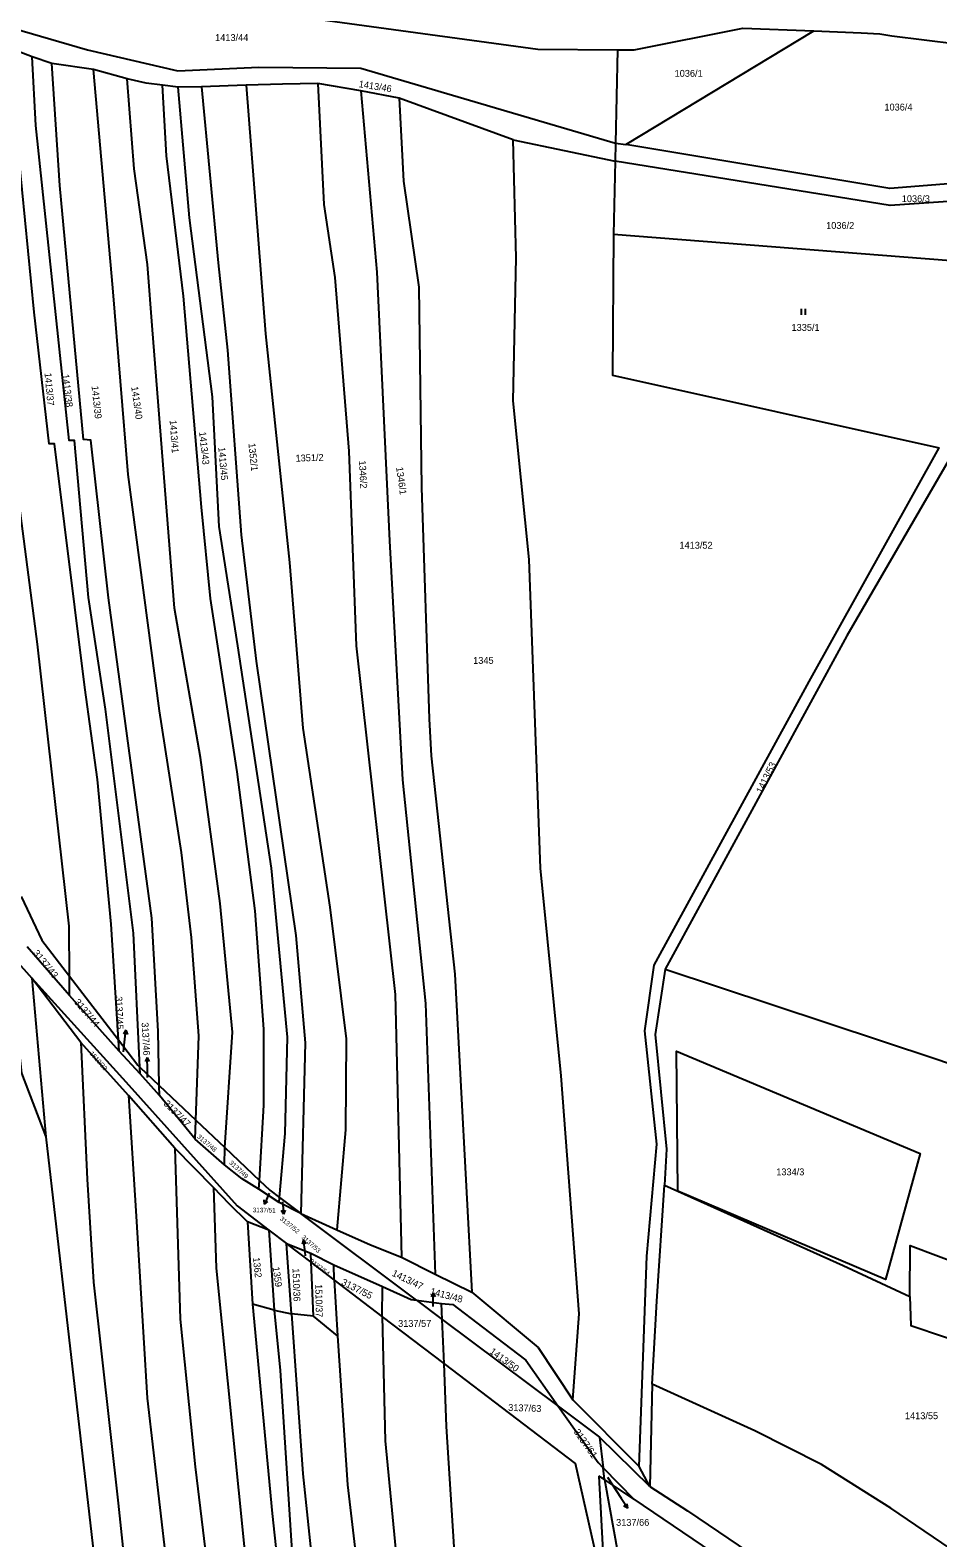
# Model space of a CAD drawing. Extents: x -776734 to -748832, y -1118122 to -976986.
# Drawn here: x -752178.5 to -751953.8, y -1116225.4 to -1115852 of the extents above; entities that cross this region are included whole.
import ezdxf

# ---------------------------------------------------------------- set-up
doc = ezdxf.new("R2010")
doc.units = 0
for name, color, linetype in [('KM_Hranice parcel', 7, 'Continuous'), ('KM_Parcelní čísla', 7, 'Continuous'), ('KM_Pop  PČ popisy', 7, 'Continuous'), ('KM_Značky kultur', 7, 'Continuous')]:
    doc.layers.add(name, color=color, linetype=linetype)

msp = doc.modelspace()

# ---------------------------------------------------------------- linework, layer by layer
at = {"layer": 'KM_Hranice parcel'}
for p, q in [((-752030.97, -1115880.3), (-751984.47, -1115852.18)), ((-752177.95, -1115858.57), (-752182.25, -1115856.92)), ((-752033.09, -1115856.85), (-752033.58, -1115879.94)), ((-752173.09, -1115860.22), (-752177.95, -1115858.57)), ((-752162.78, -1115861.71), (-752173.09, -1115860.22)), ((-752154.46, -1115864.03), (-752162.78, -1115861.71)), ((-752141.8, -1115866.12), (-752145.67, -1115865.62)), ((-752125, -1115865.59), (-752136.05, -1115866)), ((-752096.62, -1115867.02), (-752107.22, -1115865.22)), ((-752136.05, -1115866), (-752141.8, -1115866.12)), ((-752087.09, -1115868.83), (-752096.62, -1115867.02)), ((-752058.89, -1115879.11), (-752087.09, -1115868.83)), ((-752058.89, -1115879.11), (-752033.67, -1115884.41)), ((-752033.58, -1115879.94), (-752033.67, -1115884.41)), ((-752033.58, -1115879.94), (-752030.97, -1115880.3)), ((-752033.67, -1115884.41), (-752034.06, -1115902.59)), ((-751928.79, -1115910.84), (-752034.06, -1115902.59)), ((-752168.72, -1116091.06), (-752179.16, -1116078.98)), ((-752165.95, -1116102.71), (-752178.05, -1116086.74)), ((-752178.05, -1116086.74), (-752174.6, -1116126.07)), ((-752168.72, -1116091.06), (-752168.74, -1116086.25)), ((-752168.74, -1116086.25), (-752156.62, -1116102.03)), ((-752156.44, -1116104.86), (-752168.72, -1116091.06)), ((-752154.15, -1116115.8), (-752165.95, -1116102.71)), ((-752156.44, -1116104.86), (-752156.62, -1116102.03)), ((-752151.2, -1116110.49), (-752156.44, -1116104.86)), ((-752151.2, -1116110.49), (-752151.28, -1116108.79)), ((-752151.28, -1116108.79), (-752146.49, -1116113.33)), ((-752146.44, -1116115.83), (-752151.2, -1116110.49)), ((-752142.68, -1116128.9), (-752154.15, -1116115.8)), ((-752146.44, -1116115.83), (-752146.49, -1116113.33)), ((-752146.49, -1116113.33), (-752137.43, -1116121.93)), ((-752137.58, -1116126.64), (-752146.44, -1116115.83)), ((-752137.58, -1116126.64), (-752137.43, -1116121.93)), ((-752137.43, -1116121.93), (-752130.28, -1116128.71)), ((-752130.38, -1116133), (-752137.58, -1116126.64)), ((-752133.11, -1116138.65), (-752142.68, -1116128.9)), ((-752130.38, -1116133), (-752130.28, -1116128.71)), ((-752130.28, -1116128.71), (-752121.7, -1116136.85)), ((-752121.83, -1116139), (-752121.7, -1116136.85)), ((-752116.86, -1116142.29), (-752121.83, -1116139)), ((-752116.86, -1116142.29), (-752116.7, -1116141.11)), ((-752116.7, -1116141.11), (-752111.48, -1116145.02)), ((-752111.48, -1116145.02), (-752116.86, -1116142.29)), ((-752111.48, -1116145.02), (-752102.54, -1116149.13)), ((-752082.85, -1116166.49), (-752111.48, -1116145.02)), ((-752119.4, -1116149.15), (-752124.69, -1116147.15)), ((-752124.69, -1116147.15), (-752123.43, -1116167.51)), ((-752119.4, -1116149.15), (-752118.05, -1116168.97)), ((-752119.4, -1116149.15), (-752115.01, -1116152.49)), ((-752108.91, -1116157.14), (-752115.01, -1116152.49)), ((-752113.79, -1116169.94), (-752115.01, -1116152.49)), ((-752115.01, -1116152.49), (-752109.01, -1116154.88)), ((-752108.91, -1116157.14), (-752109.01, -1116154.88)), ((-752109.01, -1116154.88), (-752103.32, -1116157.78)), ((-752086.57, -1116155.88), (-752078.17, -1116160.09)), ((-752103.22, -1116161.47), (-752108.91, -1116157.14)), ((-752108.32, -1116170.48), (-752108.91, -1116157.14)), ((-752103.22, -1116161.47), (-752103.32, -1116157.78)), ((-752103.32, -1116157.78), (-752091.21, -1116163.17)), ((-752078.17, -1116160.09), (-752069.09, -1116164.51)), ((-752103.22, -1116161.47), (-752102.39, -1116175.31)), ((-752091.33, -1116170.52), (-752103.22, -1116161.47)), ((-752091.33, -1116170.52), (-752091.21, -1116163.17)), ((-752118.05, -1116168.97), (-752123.43, -1116167.51)), ((-752082.85, -1116166.49), (-752076.45, -1116171.28)), ((-752082.85, -1116166.49), (-752076.61, -1116167.35)), ((-752076.45, -1116171.28), (-752076.61, -1116167.35)), ((-752118.05, -1116168.97), (-752113.79, -1116169.94)), ((-752108.32, -1116170.48), (-752113.79, -1116169.94)), ((-752102.39, -1116175.31), (-752108.32, -1116170.48)), ((-752076.01, -1116182.2), (-752091.33, -1116170.52)), ((-752076.45, -1116171.28), (-752047.75, -1116192.79)), ((-752076.01, -1116182.2), (-752076.45, -1116171.28)), ((-752024.53, -1116187.32), (-752025.07, -1116212.63)), ((-752047.75, -1116192.79), (-752037.56, -1116200.43)), ((-752027.7, -1116207.75), (-752044.12, -1116191.2)), ((-752025.07, -1116212.63), (-752037.56, -1116200.43)), ((-752037.56, -1116200.43), (-752036.63, -1116208.05)), ((-752036.63, -1116208.05), (-752029.02, -1116215.81)), ((-752036.28, -1116210.9), (-752036.63, -1116208.05)), ((-752025.07, -1116212.63), (-752027.7, -1116207.75)), ((-752036.28, -1116210.9), (-752037.72, -1116210.11)), ((-752029.02, -1116215.81), (-752036.28, -1116210.9)), ((-752029.02, -1116215.81), (-751967.61, -1116257.33))]:
    msp.add_line(p, q, dxfattribs=at)
for points in [[(-752244.75, -1115830.41), (-752239.78, -1115832.43), (-752214.29, -1115840.49), (-752189.58, -1115849.47), (-752164.25, -1115856.85), (-752141.87, -1115862.01), (-752121.83, -1115861.15), (-752096.62, -1115861.4), (-752033.58, -1115879.94)], [(-752244.75, -1115830.41), (-752052.79, -1115856.72), (-752033.09, -1115856.85)], [(-752168.74, -1116086.25), (-752168.78, -1116073.92), (-752176.6, -1116004.07), (-752182.5, -1115958.91), (-752185.13, -1115959.87), (-752188.35, -1115934.16), (-752191.68, -1115873.68), (-752193.05, -1115853.24)], [(-752033.09, -1115856.85), (-752028.93, -1115856.83), (-752002.08, -1115851.48), (-751984.47, -1115852.18)], [(-751984.47, -1115852.18), (-751972.72, -1115852.64), (-751968.12, -1115852.9), (-751965.14, -1115853.34), (-751941.2, -1115856.37), (-751924.31, -1115858.52)], [(-752156.62, -1116102.03), (-752158.4, -1116073.41), (-752161.79, -1116037.58), (-752164.91, -1116014.77), (-752172.39, -1115954.41), (-752173.72, -1115954.45), (-752177.46, -1115921.84), (-752181.92, -1115876.22), (-752182.25, -1115856.92)], [(-752151.28, -1116108.79), (-752152.88, -1116075.63), (-752159.78, -1116020.18), (-752163.99, -1115992.47), (-752167.49, -1115953.58), (-752168.78, -1115953.58), (-752177.03, -1115875.55), (-752177.95, -1115858.57)], [(-752146.49, -1116113.33), (-752146.78, -1116099.86), (-752148.31, -1116071.93), (-752159.05, -1115992.53), (-752163.45, -1115953.53), (-752165.28, -1115953.39), (-752171.13, -1115890.47), (-752173.09, -1115860.22)], [(-752137.43, -1116121.93), (-752136.74, -1116101.01), (-752138.53, -1116076.68), (-752140.96, -1116055.66), (-752146.41, -1116020.58), (-752154.2, -1115961.99), (-752157.99, -1115915.81), (-752162.78, -1115861.71)], [(-752145.67, -1115865.62), (-752149.75, -1115865.08), (-752154.46, -1115864.03)], [(-752130.28, -1116128.71), (-752128.37, -1116100.14), (-752131.39, -1116068.3), (-752136.28, -1116032.13), (-752142.74, -1115995.11), (-752148.2, -1115926.23), (-752149.42, -1115909.99), (-752152.72, -1115886.34), (-752154.46, -1115864.03)], [(-752121.7, -1116136.85), (-752120.61, -1116118.19), (-752120.6, -1116099.39), (-752122.77, -1116070.07), (-752127.23, -1116035.69), (-752133.78, -1115992.73), (-752136.02, -1115970.08), (-752140.48, -1115917.89), (-752144.73, -1115883.11), (-752145.67, -1115865.62)], [(-752107.22, -1115865.22), (-752116.02, -1115865.32), (-752125, -1115865.59)], [(-752125, -1115865.59), (-752120.18, -1115927.16), (-752114.22, -1115983.82), (-752110.98, -1116024.87), (-752104.27, -1116069.18), (-752100.27, -1116101.79), (-752100.37, -1116124.32), (-752102.54, -1116149.13)], [(-752107.22, -1115865.22), (-752105.74, -1115895.16), (-752103.03, -1115913.21), (-752099.59, -1115956.21), (-752097.76, -1116004.48), (-752088.12, -1116090.85), (-752086.57, -1116155.88)], [(-752116.7, -1116141.11), (-752115.32, -1116125.21), (-752114.73, -1116101.39), (-752118.68, -1116059.51), (-752127.02, -1116004.45), (-752131.71, -1115974.88), (-752133.32, -1115942.8), (-752139.03, -1115898.44), (-752141.8, -1115866.12)], [(-752136.05, -1115866), (-752131.91, -1115909.64), (-752129.64, -1115931.25), (-752126.23, -1115976.95), (-752122.5, -1116008.29), (-752112.69, -1116076.23), (-752110.42, -1116102.8), (-752111.48, -1116145.02)], [(-752096.62, -1115867.02), (-752092.66, -1115911.92), (-752089.53, -1115978.49), (-752086.28, -1116037.63), (-752080.6, -1116093.06), (-752078.17, -1116160.09)], [(-752087.09, -1115868.83), (-752086.04, -1115889.38), (-752082.28, -1115915.65), (-752081.57, -1115965.22), (-752079.66, -1116022.57), (-752079.18, -1116031.72), (-752073.37, -1116085.74), (-752069.09, -1116164.51)], [(-752044.12, -1116191.2), (-752042.6, -1116169.93), (-752046.98, -1116110.96), (-752052.13, -1116059.51), (-752054.9, -1115983.09), (-752058.9, -1115943.74), (-752058.14, -1115908.39), (-752058.89, -1115879.11)], [(-751921.23, -1115887.66), (-751965.69, -1115891.2), (-752030.97, -1115880.3)], [(-751921.39, -1115892.38), (-751965.58, -1115895.4), (-752033.67, -1115884.41)], [(-752034.06, -1115902.59), (-752034.28, -1115937.4), (-751953.42, -1115955.46)], [(-752027.7, -1116207.75), (-752025.8, -1116155.61), (-752023.34, -1116127.92), (-752026.32, -1116099.82), (-752023.96, -1116083.51), (-751985.61, -1116013.3), (-751953.42, -1115955.46)], [(-751949.72, -1115956.2), (-751976.28, -1116001.97), (-752021.26, -1116084.5)], [(-752180.64, -1116066.51), (-752175.58, -1116077.34), (-752168.74, -1116086.25)], [(-752184.07, -1116078.11), (-752180.63, -1116110.3), (-752174.6, -1116126.07)], [(-752184.07, -1116078.11), (-752182.11, -1116082.25), (-752178.05, -1116086.74)], [(-752021.26, -1116084.5), (-752023.78, -1116100.69), (-752020.93, -1116129.09), (-752021.44, -1116138.03)], [(-752021.26, -1116084.5), (-751954.28, -1116106.76), (-751878.91, -1116132.52), (-751849.54, -1116138.46), (-751864.28, -1116164.24)], [(-752178.05, -1116086.74), (-752154.81, -1116112.45), (-752127.25, -1116143.17), (-752119.4, -1116149.15)], [(-752165.95, -1116102.71), (-752164.33, -1116136.55), (-752162.74, -1116162.09), (-752156.71, -1116216.83), (-752151.57, -1116265.42), (-752144.17, -1116332.21), (-752140.15, -1116365.11), (-752135.5, -1116393.73), (-752128.72, -1116429.01), (-752127.84, -1116468.06), (-752124.6, -1116508.67), (-752124.98, -1116521.91), (-752135.82, -1116514.55)], [(-752156.62, -1116102.03), (-752151.81, -1116108.29), (-752151.28, -1116108.79)], [(-752018.13, -1116139.48), (-752018.5, -1116104.86), (-751958.18, -1116130.17), (-751966.75, -1116161.42), (-752018.13, -1116139.48)], [(-752154.15, -1116115.8), (-752152.25, -1116145.68), (-752149.48, -1116190.78), (-752136.91, -1116299.1), (-752126.9, -1116382.45), (-752120.61, -1116430.42), (-752115.56, -1116478.78), (-752113, -1116508.67), (-752115.4, -1116518.05), (-752116.87, -1116525.29), (-752111.35, -1116567.65), (-752106.73, -1116619.27), (-752103.92, -1116654.37), (-752098.48, -1116721.23)], [(-752174.6, -1116126.07), (-752166.87, -1116192.95), (-752158.85, -1116263.38), (-752156.71, -1116303.51), (-752151.3, -1116341.33), (-752138.37, -1116429.18), (-752136.5, -1116462.73), (-752135.89, -1116484.99), (-752135.82, -1116514.55)], [(-752142.68, -1116128.9), (-752141.35, -1116171.25), (-752137.64, -1116207.78), (-752125.81, -1116305.36), (-752116.18, -1116388.17), (-752111.3, -1116422.2), (-752105.09, -1116478.91), (-752101.86, -1116522.09), (-752098.52, -1116553.17), (-752095.76, -1116613.19), (-752089.84, -1116678.02), (-752084.67, -1116717.26)], [(-752121.83, -1116139), (-752125.96, -1116136.49), (-752130.38, -1116133)], [(-752121.7, -1116136.85), (-752119.14, -1116139.28), (-752116.7, -1116141.11)], [(-752024.53, -1116187.32), (-752023.32, -1116166.75), (-752021.44, -1116138.03)], [(-752021.44, -1116138.03), (-752018.13, -1116139.48), (-751977.19, -1116157.92), (-751960.75, -1116165.61)], [(-752124.69, -1116147.15), (-752129.09, -1116142.72), (-752133.11, -1116138.65)], [(-752133.11, -1116138.65), (-752132.42, -1116158.63), (-752125.46, -1116227.53), (-752117.44, -1116292.6), (-752110.09, -1116359.1), (-752100.17, -1116437.88), (-752095.69, -1116474.85), (-752092.89, -1116524.7), (-752091.68, -1116540.31), (-752089.41, -1116561.36), (-752086.83, -1116606.81), (-752085.92, -1116622.13), (-752080.62, -1116669.02), (-752074.51, -1116714.34)], [(-752102.54, -1116149.13), (-752094.23, -1116152.79), (-752086.57, -1116155.88)], [(-751960.75, -1116165.61), (-751960.66, -1116152.95), (-751911.53, -1116171.43), (-751886.14, -1116180.76)], [(-752091.21, -1116163.17), (-752084.11, -1116166.31), (-752082.85, -1116166.49)], [(-752123.43, -1116167.51), (-752118.52, -1116219.33), (-752113.21, -1116269.11), (-752107.73, -1116310.35), (-752101.77, -1116359.1), (-752096.05, -1116404.78), (-752094.04, -1116419.92), (-752089.53, -1116463.02), (-752087.28, -1116481.06), (-752084.46, -1116522.63), (-752080.99, -1116553.57), (-752078.09, -1116601.02), (-752076.96, -1116622.69), (-752073.5, -1116656.29), (-752069.23, -1116691), (-752065.65, -1116711.79)], [(-752076.61, -1116167.35), (-752073.8, -1116167.62), (-752066.53, -1116173.22), (-752055.78, -1116181.41), (-752047.75, -1116192.79)], [(-752069.09, -1116164.51), (-752052.7, -1116178.22), (-752044.12, -1116191.2)], [(-751960.75, -1116165.61), (-751960.5, -1116172.81), (-751943.76, -1116178.41), (-751909.07, -1116192.07), (-751889.54, -1116201.98)], [(-752118.05, -1116168.97), (-752116.6, -1116183.9), (-752113.43, -1116232.37), (-752111.41, -1116249.39), (-752105.93, -1116293.43), (-752094.61, -1116381.9), (-752089.13, -1116422.48), (-752085.67, -1116453.92), (-752083.17, -1116484.31), (-752079.8, -1116525.75), (-752076.73, -1116555.18), (-752075.76, -1116570.66), (-752072.49, -1116627.11), (-752067.87, -1116674.42), (-752062.04, -1116710.75)], [(-752113.79, -1116169.94), (-752110.94, -1116209.53), (-752105.69, -1116259.78), (-752098.36, -1116323.38), (-752088.4, -1116395.97), (-752084.26, -1116424.45), (-752079.29, -1116481.41), (-752075.15, -1116529.39), (-752073.28, -1116546.6), (-752071, -1116582.62), (-752068.09, -1116623.34), (-752064.5, -1116659.9), (-752061.67, -1116685.28), (-752057.71, -1116708.78)], [(-752091.33, -1116170.52), (-752091.03, -1116184.27), (-752090.6, -1116201.38), (-752086.96, -1116239.19), (-752080.77, -1116290.76), (-752075.21, -1116336.04), (-752068.84, -1116386.33), (-752066.21, -1116414.12), (-752057.2, -1116499.5), (-752055.65, -1116524.83), (-752053.1, -1116572.93), (-752049.91, -1116617.58), (-752045.45, -1116660.22), (-752038.63, -1116700.1)], [(-752102.39, -1116175.31), (-752099.9, -1116212.26), (-752092.02, -1116279.66), (-752084.55, -1116341.12), (-752078.68, -1116390.57), (-752072.19, -1116452.52), (-752067.79, -1116496.71), (-752063.39, -1116563.68), (-752056.16, -1116640.19), (-752048.54, -1116704.61)], [(-752017.9, -1116408.76), (-752023.63, -1116341.02), (-752028.14, -1116300.58), (-752036.89, -1116236.27), (-752043.49, -1116206.97), (-752076.01, -1116182.2)], [(-752024.24, -1116693.56), (-752035.71, -1116608.37), (-752037.73, -1116585.85), (-752038.36, -1116560.02), (-752042.15, -1116500.69), (-752046.45, -1116458.81), (-752052.14, -1116403.78), (-752059.97, -1116326.66), (-752069.01, -1116269.52), (-752073.5, -1116227.61), (-752075.37, -1116197.8), (-752076.01, -1116182.2)], [(-751906.88, -1116257.83), (-751965.43, -1116218.03), (-751982.56, -1116207.19), (-751999.04, -1116198.88), (-752024.53, -1116187.32)], [(-752047.75, -1116192.79), (-752037.9, -1116206.75), (-752036.63, -1116208.05)], [(-752037.72, -1116210.11), (-752036.58, -1116231.72), (-752026.84, -1116301.37), (-752020.12, -1116357.18), (-752017.9, -1116408.76)], [(-752036.28, -1116210.9), (-752031.83, -1116235.64), (-752023.06, -1116294.18)], [(-752025.07, -1116212.63), (-752015.78, -1116218.71), (-751975.31, -1116246.13), (-751917.35, -1116277.21), (-751898.52, -1116290.39)]]:
    msp.add_lwpolyline(points, dxfattribs=at)
at = {"layer": 'KM_Pop  PČ popisy'}
for p, q in [((-752154.776, -1116099.655), (-752155.379, -1116100.599)), ((-752155.09, -1116102.64), (-752154.776, -1116099.655)), ((-752154.776, -1116099.655), (-752154.383, -1116100.704)), ((-752155.34, -1116105), (-752155.09, -1116102.64)), ((-752149.525, -1116106.401), (-752149.99, -1116107.419)), ((-752149.42, -1116109.4), (-752149.525, -1116106.401)), ((-752149.525, -1116106.401), (-752148.989, -1116107.384)), ((-752149.37, -1116111.38), (-752149.42, -1116109.4)), ((-752120.443, -1116142.772), (-752120.512, -1116141.655)), ((-752119.27, -1116140.01), (-752120.443, -1116142.772)), ((-752120.443, -1116142.772), (-752119.59, -1116142.046)), ((-752119.26, -1116139.99), (-752119.27, -1116140.01)), ((-752115.666, -1116145.245), (-752116.269, -1116144.301)), ((-752115.99, -1116142.17), (-752115.98, -1116142.26)), ((-752115.98, -1116142.26), (-752115.666, -1116145.245)), ((-752115.666, -1116145.245), (-752115.273, -1116144.196)), ((-752110.766, -1116151.571), (-752111.141, -1116152.626)), ((-752110.4, -1116154.55), (-752110.766, -1116151.571)), ((-752110.766, -1116151.571), (-752110.147, -1116152.504)), ((-752110.28, -1116155.56), (-752110.4, -1116154.55)), ((-752078.68, -1116164.669), (-752079.181, -1116165.67)), ((-752078.68, -1116167.67), (-752078.68, -1116164.669)), ((-752078.68, -1116164.669), (-752078.179, -1116165.67)), ((-752078.68, -1116168.08), (-752078.68, -1116167.67)), ((-752035.55, -1116210.36), (-752032.16, -1116215.53)), ((-752032.16, -1116215.53), (-752030.526, -1116218.047)), ((-752030.526, -1116218.047), (-752031.491, -1116217.48)), ((-752030.526, -1116218.047), (-752030.651, -1116216.934))]:
    msp.add_line(p, q, dxfattribs=at)
at = {"layer": 'KM_Značky kultur'}
for p, q in [((-751987.511, -1115922.51), (-751987.511, -1115921.01)), ((-751986.51, -1115922.51), (-751986.51, -1115921.01))]:
    msp.add_line(p, q, dxfattribs=at)

# ---------------------------------------------------------------- texts
at = {"layer": 'KM_Parcelní čísla'}
for s, p in [('1413/44', (-752132.67, -1115854.66)), ('1036/1', (-752018.94, -1115863.52)), ('1036/4', (-751967.01, -1115871.88)), ('1036/3', (-751962.71, -1115894.57)), ('1036/2', (-751981.43, -1115901.2)), ('1335/1', (-751990, -1115926.45)), ('1413/52', (-752017.74, -1115980.4)), ('1345', (-752068.8, -1116008.92)), ('1334/3', (-751993.78, -1116135.59)), ('3137/57', (-752087.38, -1116173.13)), ('1413/55', (-751961.93, -1116195.99)), ('3137/66', (-752033.42, -1116222.398))]:
    msp.add_text(s, height=1.7, dxfattribs=at).set_placement(p)
for s, height, rotation, p in [('1413/46', 1.7, 351, (-752097.212, -1115866.079)), ('1413/37', 1.7, 275, (-752174.896, -1115936.884)), ('1413/38', 1.7, 277, (-752170.543, -1115937.283)), ('1413/39', 1.7, 275.999997, (-752163.255, -1115940.128)), ('1413/40', 1.7, 278, (-752153.441, -1115940.328)), ('1413/41', 1.7, 274, (-752143.927, -1115948.599)), ('1413/43', 1.7, 275.999997, (-752136.635, -1115951.488)), ('1352/1', 1.7, 275.999997, (-752124.435, -1115954.348)), ('1413/45', 1.7, 275, (-752131.886, -1115955.324)), ('1351/2', 1.7, 2, (-752112.74, -1115958.849)), ('1346/2', 1.7, 273, (-752097.088, -1115958.594)), ('1346/1', 1.7, 278, (-752087.881, -1115960.268)), ('1413/53', 1.7, 64, (-751997.346, -1116041.142)), ('3137/43', 1.7, 309, (-752177.85, -1116080.614)), ('3137/44', 1.7, 310, (-752167.671, -1116092.756)), ('3137/45', 1.7, 272, (-752157.359, -1116091.289)), ('3137/46', 1.7, 273, (-752150.869, -1116097.763)), ('1510/33', 1.14, 311, (-752163.822, -1116105.477)), ('3137/47', 1.7, 315, (-752145.581, -1116117.981)), ('3137/48', 1.14, 320, (-752137.227, -1116126.225)), ('3137/49', 1.139, 318, (-752129.289, -1116132.662)), ('3137/51', 1.139, 359, (-752123.369, -1116144.735)), ('3137/52', 1.139, 321, (-752116.761, -1116146.544)), ('3137/53', 1.139, 318, (-752111.408, -1116151.091)), ('1362', 1.7, 275.999997, (-752123.325, -1116155.998)), ('3137/54', 1.14, 323, (-752109.364, -1116157.14)), ('1359', 1.7, 278, (-752118.441, -1116158.358)), ('1510/36', 1.7, 272, (-752113.529, -1116158.659)), ('1413/47', 1.7, 334, (-752089.062, -1116160.393)), ('1510/37', 1.7, 271, (-752107.879, -1116162.564)), ('3137/55', 1.7, 333, (-752101.595, -1116162.587)), ('1413/48', 1.7, 345, (-752079.59, -1116165.051)), ('1413/50', 1.7, 324, (-752064.879, -1116179.557)), ('3137/63', 1.7, 358, (-752060.163, -1116193.929)), ('3137/61', 1.7, 305, (-752044.016, -1116199.117))]:
    msp.add_text(s, height=height, rotation=rotation, dxfattribs=at).set_placement(p)

doc.saveas('drawing.dxf')
